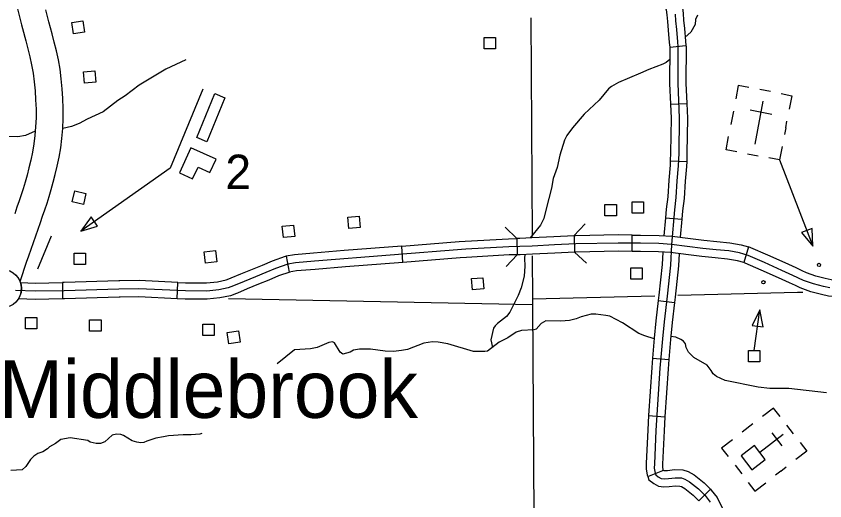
# Model space of a CAD drawing. Extents: x 1369885 to 1370219, y 379980 to 380218.
# Drawn here: x 1370050.18 to 1370079.7, y 380056.29 to 380074 of the extents above; entities that cross this region are included whole.
import ezdxf

# ---------------------------------------------------------------- set-up
doc = ezdxf.new("R2010")
doc.units = 0
for name, color, linetype in [('Level 10', 7, 'Continuous'), ('Level 24', 7, 'Continuous'), ('Level 31', 7, 'Continuous'), ('Level 32', 7, 'Continuous'), ('Level 35', 7, 'Continuous'), ('Level 38', 7, 'Continuous'), ('Level 4', 7, 'Continuous'), ('Level 5', 7, 'Continuous'), ('Level 56', 7, 'Continuous'), ('Level 57', 7, 'Continuous'), ('Level 58', 7, 'Continuous')]:
    doc.layers.add(name, color=color, linetype=linetype)

msp = doc.modelspace()

# ---------------------------------------------------------------- linework, layer by layer
at = {"layer": 'Level 10'}
for points in [[(1370050.222, 380074.268), (1370050.297, 380073.978), (1370050.375, 380073.682), (1370050.411, 380073.545), (1370050.53, 380073.097), (1370050.606, 380072.807), (1370050.678, 380072.515), (1370050.742, 380072.22), (1370050.794, 380071.914), (1370050.835, 380071.599), (1370050.866, 380071.272), (1370050.888, 380070.94), (1370050.901, 380070.608), (1370050.901, 380070.282), (1370050.888, 380069.96), (1370050.861, 380069.644), (1370050.821, 380069.335), (1370050.768, 380069.033), (1370050.707, 380068.741), (1370050.64, 380068.459), (1370050.572, 380068.193), (1370050.5, 380067.94), (1370050.428, 380067.694), (1370050.361, 380067.47), (1370050.285, 380067.252), (1370050.204, 380067.021), (1370050.122, 380066.782)], [(1370050.317, 380064.313), (1370050.405, 380064.56), (1370050.482, 380064.789), (1370050.559, 380065.016), (1370050.641, 380065.25), (1370050.723, 380065.489), (1370050.806, 380065.729), (1370050.892, 380065.97), (1370050.98, 380066.216), (1370051.063, 380066.46), (1370051.143, 380066.694), (1370051.224, 380066.924), (1370051.308, 380067.165), (1370051.382, 380067.413), (1370051.455, 380067.664), (1370051.532, 380067.932), (1370051.606, 380068.221), (1370051.678, 380068.524), (1370051.745, 380068.846), (1370051.804, 380069.187), (1370051.849, 380069.537), (1370051.88, 380069.896), (1370051.896, 380070.262), (1370051.895, 380070.629), (1370051.881, 380070.992), (1370051.857, 380071.351), (1370051.824, 380071.709), (1370051.778, 380072.063), (1370051.718, 380072.409), (1370051.647, 380072.739), (1370051.569, 380073.053), (1370051.491, 380073.351), (1370051.372, 380073.798), (1370051.337, 380073.934), (1370051.26, 380074.228)], [(1370050.153, 380064.557), (1370050.241, 380064.449), (1370050.317, 380064.313)]]:
    msp.add_lwpolyline(points, dxfattribs=at)
at = {"layer": 'Level 24'}
msp.add_circle((1370049.673, 380064.05), 0.696, dxfattribs=at)
at = {"layer": 'Level 31'}
for p, q in [((1370072.66, 380065.408), (1370072.664, 380066.005)), ((1370068.457, 380065.879), (1370068.471, 380065.283)), ((1370070.548, 380065.976), (1370070.562, 380065.38)), ((1370064.297, 380065.004), (1370064.25, 380065.599)), ((1370076.917, 380065.569), (1370076.745, 380064.998)), ((1370060.038, 380065.234), (1370060.141, 380064.646)), ((1370051.863, 380064.267), (1370051.872, 380063.67)), ((1370056.052, 380063.68), (1370056.079, 380064.276)), ((1370056.079, 380064.276), (1370056.079, 380064.276))]:
    msp.add_line(p, q, dxfattribs=at)
for points in [[(1370072.664, 380066.005), (1370072.155, 380066.009), (1370070.595, 380065.978), (1370070.548, 380065.976)], [(1370072.664, 380066.005), (1370072.97, 380066.003), (1370073.648, 380065.99), (1370074.124, 380065.962), (1370074.794, 380065.876)], [(1370079.877, 380064.072), (1370079.648, 380064.121), (1370079.279, 380064.217), (1370078.917, 380064.35), (1370078.53, 380064.532), (1370078.131, 380064.713), (1370077.497, 380064.997), (1370076.899, 380065.263), (1370076.579, 380065.36), (1370076.19, 380065.423), (1370075.727, 380065.469), (1370075.244, 380065.517), (1370074.096, 380065.665), (1370073.637, 380065.692), (1370072.966, 380065.704), (1370072.157, 380065.71), (1370070.604, 380065.68), (1370069.825, 380065.644), (1370069.016, 380065.602), (1370068.569, 380065.583), (1370068.157, 380065.574), (1370066.591, 380065.484), (1370061.062, 380065.048), (1370060.373, 380064.99), (1370060.089, 380064.94), (1370059.645, 380064.788), (1370059.29, 380064.634), (1370058.912, 380064.481), (1370058.496, 380064.31), (1370058.111, 380064.149), (1370057.921, 380064.076), (1370057.57, 380064.004), (1370057.138, 380063.959), (1370056.356, 380063.964), (1370054.657, 380064.043), (1370053.927, 380064.032), (1370051.931, 380063.969), (1370050.871, 380063.953), (1370050.151, 380063.979)], [(1370064.25, 380065.599), (1370066.344, 380065.764)], [(1370066.344, 380065.764), (1370066.571, 380065.782), (1370068.145, 380065.872), (1370068.457, 380065.879)], [(1370070.548, 380065.976), (1370069.81, 380065.942), (1370069.002, 380065.9), (1370068.559, 380065.882), (1370068.457, 380065.879)], [(1370074.794, 380065.876), (1370075.278, 380065.813), (1370075.756, 380065.765), (1370076.228, 380065.719), (1370076.646, 380065.651), (1370076.917, 380065.569)], [(1370062.156, 380065.434), (1370061.037, 380065.345), (1370060.335, 380065.286), (1370060.038, 380065.234)], [(1370064.25, 380065.599), (1370062.156, 380065.434)], [(1370078.876, 380064.699), (1370078.655, 380064.802), (1370078.254, 380064.985), (1370077.619, 380065.269), (1370077.003, 380065.543), (1370076.917, 380065.569)], [(1370058.025, 380064.437), (1370058.382, 380064.586), (1370058.799, 380064.757), (1370059.174, 380064.909), (1370059.537, 380065.067), (1370060.014, 380065.23), (1370060.038, 380065.234)], [(1370066.391, 380065.169), (1370064.297, 380065.004)], [(1370068.471, 380065.283), (1370068.169, 380065.276), (1370066.612, 380065.187), (1370066.391, 380065.169)], [(1370070.576, 380065.38), (1370069.84, 380065.346), (1370069.03, 380065.304), (1370068.578, 380065.285), (1370068.471, 380065.283)], [(1370072.66, 380065.408), (1370072.159, 380065.412), (1370070.614, 380065.382), (1370070.576, 380065.38)], [(1370074.718, 380065.284), (1370074.068, 380065.368), (1370073.626, 380065.394), (1370072.963, 380065.406), (1370072.66, 380065.408)], [(1370076.745, 380064.998), (1370076.511, 380065.068), (1370076.151, 380065.127), (1370075.698, 380065.172), (1370075.21, 380065.22), (1370074.718, 380065.284)], [(1370062.203, 380064.839), (1370061.086, 380064.751), (1370060.412, 380064.694), (1370060.141, 380064.646)], [(1370064.297, 380065.004), (1370062.203, 380064.839)], [(1370078.622, 380064.159), (1370078.405, 380064.261), (1370078.009, 380064.441), (1370077.376, 380064.725), (1370076.795, 380064.983), (1370076.745, 380064.998)], [(1370060.163, 380064.65), (1370059.753, 380064.51), (1370059.405, 380064.359), (1370059.025, 380064.205), (1370058.611, 380064.034), (1370058.255, 380063.886)], [(1370080.808, 380064.297), (1370080.193, 380064.339), (1370079.924, 380064.367), (1370079.716, 380064.411), (1370079.369, 380064.502), (1370079.032, 380064.626), (1370078.876, 380064.699)], [(1370050.261, 380063.677), (1370050.305, 380063.756), (1370050.346, 380063.856), (1370050.363, 380063.956), (1370050.371, 380064.073), (1370050.356, 380064.186), (1370050.333, 380064.271), (1370050.874, 380064.252), (1370051.863, 380064.267)], [(1370053.963, 380064.331), (1370053.92, 380064.331), (1370051.924, 380064.268), (1370051.863, 380064.267)], [(1370056.079, 380064.276), (1370054.662, 380064.341), (1370053.963, 380064.331)], [(1370056.079, 380064.276), (1370056.364, 380064.263), (1370057.124, 380064.257), (1370057.524, 380064.299), (1370057.837, 380064.363), (1370058, 380064.426), (1370058.025, 380064.437)], [(1370080.767, 380063.702), (1370080.142, 380063.745), (1370079.831, 380063.777), (1370079.579, 380063.83), (1370079.19, 380063.932), (1370078.802, 380064.075), (1370078.622, 380064.159)], [(1370051.872, 380063.67), (1370050.868, 380063.655), (1370050.261, 380063.677)], [(1370053.971, 380063.735), (1370053.933, 380063.734), (1370051.938, 380063.671), (1370051.872, 380063.67)], [(1370056.052, 380063.68), (1370054.653, 380063.744), (1370053.971, 380063.735)], [(1370058.255, 380063.886), (1370058.222, 380063.872), (1370058.005, 380063.789), (1370057.616, 380063.709), (1370057.153, 380063.661), (1370056.349, 380063.666), (1370056.052, 380063.68)]]:
    msp.add_lwpolyline(points, dxfattribs=at)
at = {"layer": 'Level 32'}
for p, q in [((1370074.036, 380072.872), (1370074.63, 380072.932)), ((1370074.066, 380070.79), (1370074.662, 380070.815)), ((1370074.058, 380068.715), (1370074.655, 380068.691)), ((1370073.881, 380066.637), (1370074.475, 380066.586)), ((1370073.62, 380063.608), (1370074.212, 380063.539)), ((1370073.41, 380061.509), (1370074.004, 380061.458)), ((1370073.265, 380059.408), (1370073.861, 380059.369)), ((1370073.231, 380057.186), (1370073.787, 380057.402)), ((1370075.102, 380056.295), (1370075.524, 380056.717))]:
    msp.add_line(p, q, dxfattribs=at)
for points in [[(1370073.661, 380074.917), (1370073.778, 380074.92), (1370074.027, 380074.905), (1370074.212, 380074.806), (1370074.313, 380074.706), (1370074.407, 380074.58), (1370074.492, 380074.4), (1370074.529, 380074.099), (1370074.544, 380073.852), (1370074.577, 380073.546), (1370074.614, 380073.092), (1370074.63, 380072.932)], [(1370073.675, 380074.321), (1370073.767, 380074.323), (1370073.857, 380074.318), (1370073.861, 380074.314), (1370073.894, 380074.27), (1370073.912, 380074.232), (1370073.935, 380074.044), (1370073.95, 380073.801), (1370073.983, 380073.49), (1370074.019, 380073.038), (1370074.036, 380072.872)], [(1370074.232, 380074.071), (1370074.247, 380073.827), (1370074.28, 380073.518), (1370074.317, 380073.065), (1370074.335, 380072.887), (1370074.332, 380071.551), (1370074.386, 380070.275), (1370074.368, 380069), (1370074.35, 380068.533), (1370074.301, 380067.989), (1370074.265, 380067.373), (1370074.205, 380066.922), (1370074.096, 380065.665)], [(1370074.036, 380072.872), (1370074.036, 380072.872), (1370074.033, 380071.545), (1370074.066, 380070.79)], [(1370074.63, 380072.932), (1370074.633, 380072.901), (1370074.63, 380071.557), (1370074.662, 380070.815)], [(1370074.066, 380070.79), (1370074.088, 380070.271), (1370074.07, 380069.008), (1370074.058, 380068.715)], [(1370074.662, 380070.815), (1370074.684, 380070.279), (1370074.666, 380068.992), (1370074.655, 380068.691)], [(1370074.058, 380068.715), (1370074.052, 380068.552), (1370074.004, 380068.011), (1370073.968, 380067.401), (1370073.908, 380066.955), (1370073.881, 380066.637)], [(1370074.655, 380068.691), (1370074.648, 380068.514), (1370074.599, 380067.967), (1370074.562, 380067.344), (1370074.501, 380066.89), (1370074.475, 380066.586)], [(1370073.881, 380066.637), (1370073.824, 380065.98)], [(1370074.475, 380066.586), (1370074.418, 380065.924)], [(1370074.096, 380065.665), (1370074.06, 380064.906), (1370073.939, 380063.77), (1370073.83, 380062.839), (1370073.77, 380062.21), (1370073.677, 380061.143), (1370073.529, 380058.868), (1370073.476, 380057.649), (1370073.472, 380057.486), (1370073.502, 380057.311), (1370073.528, 380057.244), (1370073.617, 380057.174), (1370073.721, 380057.114), (1370073.833, 380057.101), (1370073.988, 380057.11), (1370074.229, 380057.14), (1370074.463, 380057.133), (1370074.589, 380057.092), (1370074.76, 380056.995), (1370075.091, 380056.728), (1370075.329, 380056.49), (1370075.514, 380056.252)], [(1370073.784, 380065.385), (1370073.762, 380064.929), (1370073.643, 380063.803), (1370073.62, 380063.608)], [(1370074.379, 380065.328), (1370074.357, 380064.883), (1370074.236, 380063.737), (1370074.212, 380063.539)], [(1370073.62, 380063.608), (1370073.534, 380062.871), (1370073.473, 380062.237), (1370073.41, 380061.509)], [(1370074.212, 380063.539), (1370074.127, 380062.807), (1370074.067, 380062.183), (1370074.004, 380061.458)], [(1370073.41, 380061.509), (1370073.38, 380061.165), (1370073.265, 380059.408)], [(1370074.004, 380061.458), (1370073.975, 380061.12), (1370073.861, 380059.369)], [(1370073.265, 380059.408), (1370073.231, 380058.884), (1370073.178, 380057.659), (1370073.173, 380057.464), (1370073.213, 380057.231), (1370073.231, 380057.186)], [(1370073.861, 380059.369), (1370073.827, 380058.852), (1370073.774, 380057.64), (1370073.771, 380057.508), (1370073.791, 380057.391), (1370073.787, 380057.402)], [(1370073.231, 380057.186), (1370073.279, 380057.061), (1370073.45, 380056.926), (1370073.625, 380056.825), (1370073.824, 380056.801), (1370074.015, 380056.813), (1370074.243, 380056.841), (1370074.411, 380056.836), (1370074.469, 380056.817), (1370074.592, 380056.748), (1370074.891, 380056.506), (1370075.102, 380056.295)], [(1370073.777, 380057.428), (1370073.785, 380057.421), (1370073.817, 380057.403), (1370073.841, 380057.4), (1370073.96, 380057.408), (1370074.216, 380057.439), (1370074.515, 380057.43), (1370074.71, 380057.366), (1370074.929, 380057.243), (1370075.291, 380056.95), (1370075.524, 380056.717)], [(1370075.524, 380056.717), (1370075.553, 380056.688), (1370075.768, 380056.412), (1370075.956, 380056.039), (1370076.021, 380055.683), (1370076.061, 380055.351), (1370076.069, 380054.991), (1370076.051, 380054.605), (1370076.052, 380054.528)]]:
    msp.add_lwpolyline(points, dxfattribs=at)
at = {"layer": 'Level 35'}
for points in [[(1370075.046, 380074.039), (1370074.972, 380073.873), (1370074.96, 380073.699), (1370074.809, 380073.415), (1370074.602, 380073.233)], [(1370056.374, 380072.4), (1370055.646, 380072.059), (1370054.662, 380071.479), (1370054.158, 380071.085), (1370053.893, 380070.925), (1370053.357, 380070.502), (1370052.769, 380070.241), (1370052.473, 380070.077), (1370052.202, 380069.969), (1370051.88, 380069.895)], [(1370074.035, 380072.416), (1370073.903, 380072.309), (1370073.788, 380072.243), (1370073.268, 380072.05), (1370072.972, 380071.923), (1370072.169, 380071.572), (1370071.911, 380071.436), (1370071.803, 380071.349), (1370071.466, 380070.932), (1370070.91, 380070.417), (1370070.484, 380069.918), (1370070.274, 380069.645), (1370070.199, 380069.475), (1370070.021, 380068.923), (1370069.924, 380068.47), (1370069.781, 380068.075), (1370069.716, 380067.722), (1370069.529, 380066.963)], [(1370050.874, 380069.794), (1370050.515, 380069.643), (1370050.243, 380069.598), (1370049.841, 380069.606)], [(1370069.529, 380066.963), (1370069.444, 380066.61), (1370069.396, 380066.509), (1370069.317, 380066.367), (1370068.935, 380065.897)], [(1370068.75, 380065.292), (1370068.734, 380065.161), (1370068.742, 380064.87), (1370068.726, 380064.503), (1370068.612, 380064.073), (1370068.505, 380063.799), (1370068.202, 380063.184), (1370068.079, 380063.029), (1370067.749, 380062.771), (1370067.661, 380062.685), (1370067.608, 380062.6), (1370067.505, 380062.174), (1370067.562, 380061.893)], [(1370073.47, 380062.21), (1370073.122, 380062.317), (1370072.909, 380062.402), (1370072.309, 380062.794), (1370071.849, 380063.035), (1370071.709, 380063.071), (1370071.338, 380063.12), (1370071.171, 380063.119), (1370070.797, 380063.012), (1370070.624, 380062.939), (1370070.372, 380062.887), (1370070.059, 380062.862), (1370069.514, 380062.869), (1370069.346, 380062.776), (1370069.166, 380062.571), (1370069.071, 380062.537), (1370068.627, 380062.515), (1370068.43, 380062.453), (1370068.127, 380062.253), (1370067.806, 380062.092), (1370067.383, 380061.768), (1370067.284, 380061.753), (1370066.871, 380061.748), (1370065.933, 380062.035), (1370065.585, 380062.092), (1370065.378, 380062.106), (1370065.058, 380062.056), (1370064.461, 380061.827), (1370064.248, 380061.784), (1370063.955, 380061.751), (1370063.645, 380061.766), (1370063.11, 380061.841), (1370062.709, 380061.841), (1370062.488, 380061.799), (1370062.375, 380061.723), (1370062.099, 380061.647), (1370062.01, 380061.724), (1370061.797, 380062.061), (1370061.72, 380062.102), (1370061.586, 380062.082), (1370061.162, 380061.894), (1370060.918, 380061.843), (1370060.343, 380061.809), (1370059.708, 380061.294)], [(1370075.749, 380060.834), (1370075.623, 380060.938), (1370075.553, 380061.06), (1370075.397, 380061.253), (1370074.914, 380061.536), (1370074.721, 380061.721), (1370074.632, 380061.892), (1370074.606, 380062.026), (1370074.538, 380062.129), (1370074.439, 380062.189), (1370074.253, 380062.271), (1370074.078, 380062.299)], [(1370079.759, 380060.246), (1370078.388, 380060.4), (1370077.685, 380060.402), (1370077.27, 380060.45), (1370076.059, 380060.696), (1370075.749, 380060.834)], [(1370056.952, 380058.754), (1370056.883, 380058.727), (1370056.568, 380058.701), (1370056.274, 380058.7), (1370055.737, 380058.675), (1370055.56, 380058.634), (1370055.28, 380058.587), (1370054.95, 380058.476), (1370054.836, 380058.425), (1370054.726, 380058.41), (1370054.582, 380058.433), (1370054.414, 380058.488), (1370054.09, 380058.685), (1370054.001, 380058.715), (1370053.838, 380058.734), (1370053.684, 380058.689), (1370053.41, 380058.446), (1370053.257, 380058.389), (1370053.094, 380058.388), (1370052.882, 380058.434), (1370052.797, 380058.495), (1370052.148, 380058.601), (1370051.808, 380058.53), (1370051.617, 380058.394), (1370051.389, 380058.273), (1370051.32, 380058.199), (1370051.148, 380058.09), (1370050.968, 380058.021), (1370050.82, 380057.932), (1370050.704, 380057.805), (1370050.525, 380057.549), (1370050.39, 380057.433), (1370049.986, 380057.401)]]:
    msp.add_lwpolyline(points, dxfattribs=at)
at = {"layer": 'Level 38'}
for points in [[(1370070.538, 380065.976), (1370070.943, 380066.414)], [(1370068.023, 380066.29), (1370068.456, 380065.879)], [(1370068.472, 380065.283), (1370068.062, 380064.85)], [(1370071, 380064.975), (1370070.562, 380065.38)]]:
    msp.add_lwpolyline(points, dxfattribs=at)
at = {"layer": 'Level 4'}
for points in [[(1370068.968, 380073.944), (1370069.016, 380065.957)], [(1370069.02, 380065.25), (1370069.029, 380063.666), (1370069.031, 380063.449), (1370069.157, 380042.282), (1370069.158, 380042.172), (1370069.189, 380037.721)]]:
    msp.add_lwpolyline(points, dxfattribs=at)
at = {"layer": 'Level 5'}
for points in [[(1370069.031, 380063.449), (1370057.927, 380063.676)], [(1370073.49, 380063.776), (1370069.029, 380063.666)], [(1370078.894, 380063.907), (1370078.695, 380063.904), (1370074.326, 380063.797)]]:
    msp.add_lwpolyline(points, dxfattribs=at)
at = {"layer": 'Level 56'}
for points in [[(1370052.267, 380073.355), (1370052.205, 380073.764), (1370052.616, 380073.826), (1370052.677, 380073.417)], [(1370067.262, 380072.81), (1370067.262, 380073.224), (1370067.677, 380073.224), (1370067.677, 380072.81)], [(1370052.667, 380071.552), (1370052.63, 380071.964), (1370053.044, 380072.001), (1370053.08, 380071.588)], [(1370057.134, 380069.41), (1370056.766, 380069.562), (1370057.427, 380071.171), (1370057.795, 380071.02)], [(1370052.225, 380067.214), (1370052.321, 380067.616), (1370052.725, 380067.52), (1370052.629, 380067.117)], [(1370072.66, 380066.808), (1370072.66, 380067.222), (1370073.075, 380067.222), (1370073.075, 380066.808)], [(1370071.673, 380066.703), (1370071.673, 380067.117), (1370072.089, 380067.117), (1370072.089, 380066.703)], [(1370053.146, 380066.333), (1370052.913, 380066.665), (1370052.532, 380066.15)], [(1370062.32, 380066.246), (1370062.285, 380066.659), (1370062.699, 380066.693), (1370062.734, 380066.281)], [(1370059.93, 380065.915), (1370059.891, 380066.327), (1370060.304, 380066.367), (1370060.344, 380065.955)], [(1370057.091, 380064.979), (1370057.043, 380065.39), (1370057.455, 380065.439), (1370057.503, 380065.027)], [(1370052.292, 380064.926), (1370052.292, 380065.34), (1370052.707, 380065.34), (1370052.707, 380064.926)], [(1370072.613, 380064.396), (1370072.613, 380064.81), (1370073.028, 380064.81), (1370073.028, 380064.396)], [(1370066.83, 380064.005), (1370066.801, 380064.418), (1370067.215, 380064.447), (1370067.244, 380064.034)], [(1370077.043, 380062.703), (1370077.444, 380062.647), (1370077.327, 380063.278)], [(1370050.519, 380062.576), (1370050.519, 380062.99), (1370050.935, 380062.99), (1370050.935, 380062.576)], [(1370052.859, 380062.494), (1370052.859, 380062.908), (1370053.274, 380062.908), (1370053.274, 380062.494)], [(1370056.987, 380062.336), (1370056.987, 380062.75), (1370057.402, 380062.75), (1370057.402, 380062.336)], [(1370057.943, 380062.03), (1370057.88, 380062.439), (1370058.291, 380062.502), (1370058.354, 380062.093)], [(1370076.913, 380061.377), (1370076.913, 380061.791), (1370077.329, 380061.791), (1370077.329, 380061.377)]]:
    msp.add_lwpolyline(points, close=True, dxfattribs=at)
for points in [[(1370056.992, 380071.337), (1370055.802, 380068.445)], [(1370055.802, 380068.445), (1370052.532, 380066.15)], [(1370051.451, 380065.969), (1370050.951, 380064.755)], [(1370077.121, 380061.791), (1370077.327, 380063.278)]]:
    msp.add_lwpolyline(points, dxfattribs=at)
msp.add_circle((1370077.456, 380064.281), 0.0597, dxfattribs=at)
at = {"layer": 'Level 57'}
for p, q in [((1370077.713, 380071.243), (1370077.322, 380071.317)), ((1370077.441, 380070.89), (1370077.145, 380069.326)), ((1370076.362, 380070.534), (1370076.269, 380070.045)), ((1370076.977, 380070.573), (1370077.762, 380070.424)), ((1370078.27, 380069.923), (1370078.316, 380070.164)), ((1370077.293, 380070.108), (1370077.293, 380070.108)), ((1370077.293, 380070.108), (1370077.293, 380070.108)), ((1370078.27, 380069.923), (1370078.224, 380069.675)), ((1370076.878, 380068.972), (1370077.269, 380068.898)), ((1370077.069, 380059.105), (1370076.676, 380058.8)), ((1370078.551, 380058.74), (1370078.307, 380059.054)), ((1370078.176, 380058.719), (1370077.329, 380058.064)), ((1370077.758, 380058.773), (1370078.123, 380058.301)), ((1370076.42, 380057.593), (1370076.663, 380057.279)), ((1370078.093, 380057.382), (1370078.286, 380057.532)), ((1370078.093, 380057.382), (1370077.893, 380057.227))]:
    msp.add_line(p, q, dxfattribs=at)
for points in [[(1370076.929, 380071.392), (1370076.538, 380071.466), (1370076.446, 380070.977)], [(1370078.102, 380071.17), (1370078.492, 380071.096), (1370078.4, 380070.607)], [(1370076.485, 380069.047), (1370076.094, 380069.121), (1370076.187, 380069.609)], [(1370078.141, 380069.239), (1370078.048, 380068.751), (1370077.658, 380068.825)], [(1370078.048, 380068.751), (1370079.258, 380065.599)], [(1370078.062, 380059.37), (1370077.819, 380059.685), (1370077.426, 380059.381)], [(1370076.325, 380058.529), (1370075.931, 380058.224), (1370076.175, 380057.91)], [(1370078.793, 380058.427), (1370079.036, 380058.112), (1370078.643, 380057.808)], [(1370076.905, 380056.966), (1370077.149, 380056.651), (1370077.542, 380056.956)]]:
    msp.add_lwpolyline(points, dxfattribs=at)
for points in [[(1370079.23, 380066.24), (1370078.851, 380066.095), (1370079.258, 380065.599)], [(1370077.035, 380057.43), (1370077.526, 380057.81), (1370077.132, 380058.319), (1370076.641, 380057.939)]]:
    msp.add_lwpolyline(points, close=True, dxfattribs=at)
msp.add_circle((1370079.486, 380064.913), 0.0597, dxfattribs=at)
at = {"layer": 'Level 58'}
msp.add_lwpolyline([(1370056.559, 380069.196), (1370056.134, 380068.28), (1370056.618, 380068.055), (1370056.819, 380068.489), (1370057.252, 380068.288), (1370057.476, 380068.771)], close=True, dxfattribs=at)

# ---------------------------------------------------------------- texts
at = {"layer": 'Level 24'}
msp.add_text('Middlebrook', height=2.10029, dxfattribs=at).set_placement((1370049.543, 380059.325))
at = {"layer": 'Level 58'}
msp.add_text('2', height=1.26, dxfattribs=at).set_placement((1370057.815, 380067.681))

doc.saveas('drawing.dxf')
